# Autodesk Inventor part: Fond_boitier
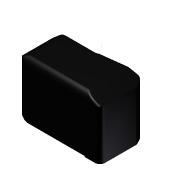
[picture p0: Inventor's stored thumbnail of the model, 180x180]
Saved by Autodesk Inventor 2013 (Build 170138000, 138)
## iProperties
Created: 2011-07
Part Number: Fond_boitier
Document SubType Name: Modeling
Designer: domi
Density: 1 g/cm^3
Material: Générique
Author: domi
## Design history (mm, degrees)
sketch "Esquisse1"
  geometry: L1 (-13.986, -11.692)-(16.704, -11.692) reference; L2 (18.504, -9.892)-(18.504, 4.208) reference; L3 (18.352, 4.844)-(17.078, 7.344) reference; L4 (15.831, 8.108)-(12.304, 8.108) reference; L5 (9.472, 9.948)-(7.197, 15.058) reference; L6 (6.731, 15.749)-(4.851, 17.696) reference; L7 (-10.621, 14.519)-(-16.593, 4.961) reference; L8 (16.704, -10.292)-(-13.986, -10.292) reference; L9 (-15.406, 4.219)-(-9.678, 13.386) reference; L10 (4.275, 16.278)-(5.724, 14.777) reference; L11 (5.918, 14.489)-(8.193, 9.378) reference; L12 (12.304, 6.708)-(15.831, 6.708) reference; L13 (15.831, 6.708)-(17.104, 4.208) reference; L14 (17.104, 4.208)-(17.104, -9.892) reference; L15 (16.704, -12.092)-(-13.986, -12.092); L16 (-16.932, 5.173)-(-10.891, 14.841); L17 (5.017, 18.1)-(7.018, 16.027); L18 (7.562, 15.221)-(9.838, 10.11); L19 (12.304, 8.508)-(15.831, 8.508); L20 (17.434, 7.526)-(18.708, 5.026); L21 (18.904, 4.208)-(18.904, -9.892); A1 r 1.8 centre (16.704, -9.892) between (16.704, -11.692) and (18.504, -9.892) reference; A2 r 1.4 centre (17.104, 4.208) between (18.504, 4.208) and (18.352, 4.844) reference; A3 r 1.4 centre (15.831, 6.708) between (17.078, 7.344) and (15.831, 8.108) reference; A4 r 3.1 centre (12.304, 11.208) between (9.472, 9.948) and (12.304, 8.108) reference; A5 r 2.4 centre (5.004, 14.082) between (7.197, 15.058) and (6.731, 15.749) reference; A6 r 44.4 centre (5.904, -26.692) between (4.851, 17.696) and (-10.621, 14.519) reference; A7 r 21.8 centre (1.894, -6.592) between (-16.593, 4.961) and (-19.878, -5.495) reference; A8 r 5.9 centre (-13.986, -5.792) between (-19.878, -5.495) and (-13.986, -11.692) reference; A9 r 4.5 centre (-13.986, -5.792) between (-18.48, -5.565) and (-13.986, -10.292) reference; A10 r 20.4 centre (1.894, -6.592) between (-15.406, 4.219) and (-18.48, -5.565) reference; A11 r 43 centre (5.904, -26.692) between (4.275, 16.278) and (-9.678, 13.386) reference; A12 r 1 centre (5.004, 14.082) between (5.918, 14.489) and (5.724, 14.777) reference; A13 r 4.5 centre (12.304, 11.208) between (8.193, 9.378) and (12.304, 6.708) reference; A14 r 0.4 centre (16.704, -9.892) between (16.704, -10.292) and (17.104, -9.892) reference; A15 r 6.3 centre (-13.986, -5.792) between (-20.278, -5.475) and (-13.986, -12.092); A16 r 22.2 centre (1.894, -6.592) between (-16.932, 5.173) and (-20.278, -5.475); A17 r 44.8 centre (5.904, -26.692) between (5.017, 18.1) and (-10.891, 14.841); A18 r 2.8 centre (5.004, 14.082) between (7.562, 15.221) and (7.018, 16.027); A19 r 2.7 centre (12.304, 11.208) between (9.838, 10.11) and (12.304, 8.508); A20 r 1.8 centre (15.831, 6.708) between (17.434, 7.526) and (15.831, 8.508); A21 r 1.8 centre (17.104, 4.208) between (18.904, 4.208) and (18.708, 5.026); A22 r 2.2 centre (16.704, -9.892) between (16.704, -12.092) and (18.904, -9.892); 1 further point
  constraints: 16 point on circle, 14 end point, 8 centre point, 14 other
  dimensions: "d0" = 1.8 distance between parallel lines of L8 L15
extrude "Corps" new body sketch "Esquisse1" distance "d1" = 25.5; taper "d2" = 0 deg
node "Plan de construction1"
sketch "Esquisse4"
  geometry: L1 (-16.704, -12.092)-(13.986, -12.092) reference; L2 (16.932, 5.173)-(10.891, 14.841) reference; L3 (-5.017, 18.1)-(-7.018, 16.027) reference; L4 (-7.562, 15.221)-(-9.838, 10.11) reference; L5 (-12.304, 8.508)-(-15.831, 8.508) reference; L6 (-17.434, 7.526)-(-18.708, 5.026) reference; L7 (-18.904, 4.208)-(-18.904, -9.892) reference; C1 r 1.77 at (1.596, 9.208) reference; A1 r 6.3 centre (13.986, -5.792) between (13.986, -12.092) and (20.278, -5.475) reference; A2 r 22.2 centre (-1.894, -6.592) between (20.278, -5.475) and (16.932, 5.173) reference; A3 r 44.8 centre (-5.904, -26.692) between (10.891, 14.841) and (-5.017, 18.1) reference; A4 r 2.8 centre (-5.004, 14.082) between (-7.018, 16.027) and (-7.562, 15.221) reference; A5 r 2.7 centre (-12.304, 11.208) between (-12.304, 8.508) and (-9.838, 10.11) reference; A6 r 1.8 centre (-15.831, 6.708) between (-15.831, 8.508) and (-17.434, 7.526) reference; A7 r 1.8 centre (-17.104, 4.208) between (-18.708, 5.026) and (-18.904, 4.208) reference; A8 r 2.2 centre (-16.704, -9.892) between (-18.904, -9.892) and (-16.704, -12.092) reference; 1 further point
  node "Référence2"
node "Axe de construction1"
sketch "Esquisse5"
  geometry: L1 (13.986, -12.092)-(-16.704, -12.092) reference; L2 (-18.904, -9.892)-(-18.904, 4.208) reference; L3 (-18.708, 5.026)-(-17.434, 7.526) reference; L4 (-15.831, 8.508)-(-12.304, 8.508) reference; L5 (-9.838, 10.11)-(-7.562, 15.221) reference; L6 (-7.018, 16.027)-(-5.017, 18.1) reference; L7 (10.891, 14.841)-(16.932, 5.173) reference; L8 (16.473, 5.908)-(1.596, 5.908); L9 (-12.304, 8.508)-(-2.132, 7.614); A1 r 6.3 centre (13.986, -5.792) between (13.986, -12.092) and (20.278, -5.475) reference; A2 r 2.2 centre (-16.704, -9.892) between (-18.904, -9.892) and (-16.704, -12.092) reference; A3 r 1.8 centre (-17.104, 4.208) between (-18.708, 5.026) and (-18.904, 4.208) reference; A4 r 1.8 centre (-15.831, 6.708) between (-15.831, 8.508) and (-17.434, 7.526) reference; A5 r 2.7 centre (-12.304, 11.208) between (-12.304, 8.508) and (-9.838, 10.11) reference; A6 r 2.8 centre (-5.004, 14.082) between (-7.018, 16.027) and (-7.562, 15.221) reference; A7 r 44.8 centre (-5.904, -26.692) between (10.891, 14.841) and (-5.017, 18.1) reference; A8 r 22.2 centre (-1.894, -6.592) between (20.278, -5.475) and (16.932, 5.173) reference; A9 r 3.3 centre (1.596, 9.208) between (-0.834, 6.975) and (1.596, 5.908); A10 r 2 centre (-2.307, 5.622) between (-0.834, 6.975) and (-2.132, 7.614); 2 further points
  constraints: 4 end point, 4 point on circle, 3 tangent, 2 centre point, 1 coincident, 1 parallel, 1 point on line
  dimensions: "d10" = 6.6 diameter of A9; "d108" = 2 radius of A10
extrude "Complement corps" cut sketch "Esquisse5" stored distance "d11" = 1.8; taper "d12" = 0 deg
sketch "Esquisse6"
  geometry: L1 (0, 0)-(0, 25.5) reference; L2 (30.69, 0)-(0, 0) reference; L3 (30.69, 0)-(30.69, 25.5) reference; L4 (32.89, 0)-(32.89, 25.5) reference; L5 (32.89, 22.5)-(25.89, 25.5); L6 (25.89, 25.5)-(32.89, 25.5); L7 (32.89, 25.5)-(32.89, 22.5); L8 (30.69, 25.5)-(0, 25.5) reference; 1 further point
  constraints: 6 end point, 1 collinear, 1 perpendicular, 1 point on line
  dimensions: "d14" = 3 distance of L4.end L5.start; "d15" = 7 distance of L5.end L4.end
extrude "Chanfrein 1" cut sketch "Esquisse6" stored distance "d16" = 1.8; taper "d17" = 0 deg
sketch "Esquisse7"
  geometry: L1 (0, 0)-(-22.5, 0) reference; L2 (0, 14.1)-(0, 0) reference; L3 (0, 14.1)-(-22.5, 14.1) reference; L4 (0, -2.2)-(-25.5, -2.2) reference; L5 (0, -2.2)-(-23.443, -2.2) reference; L6 (-25.6, 18.329)-(-25.6, 16.6) reference; L7 (-25.6, 16.6)-(-25.6, 14.6) reference; L8 (-25.6, 4.417)-(-25.6, 14.6) reference; L9 (-25.6, -2.2)-(-25.6, 4.417) reference; L10 (-22.6, 0.8)-(-25.6, 0.8); L11 (-22.6, 0.8)-(-22.6, -2.2); L12 (-22.6, -2.2)-(-25.6, -2.2); L13 (-25.6, -2.2)-(-25.6, 0.8); L14 (-25.6, -2.2)-(-25.6, 18.329) reference; L15 (-23.443, -2.2)-(-25.5, -2.2) reference; L16 (-22.5, 14.1)-(-22.5, 0) reference; A1 r 3 centre (-22.6, 0.8) between (-25.6, 0.8) and (-22.6, -2.2); 1 further point
  constraints: 8 end point, 4 tangent, 2 perpendicular, 2 point on circle, 2 point on line, 1 centre point, 1 collinear
  dimensions: "d18" = 6 diameter of A1
extrude "Arrondi1" cut sketch "Esquisse7" stored distance "d19" = 1.8; taper "d20" = 0 deg
fillet "Congé1" dims "d53" = 1
node "Plan de construction chanfrein 2"
  node "Axe de construction2"
sketch "Esquisse8"
  geometry: L1 (11.1, -11.807)-(11.1, -8.084); L2 (11.1, -11.807)-(11.1, -17.224); L3 (0, 15.601)-(0, -2) reference; L4 (-11, -2)-(-11, -12.287) reference; L5 (-11, -12.287)-(-25.5, -12.287) reference; L6 (-25.5, -12.287)-(-25.5, 17.851) reference; L7 (-25.5, 17.851)-(-2.9, 17.851) reference; L8 (-6, -2)-(0, -1); L9 (-8.744, -2.457)-(0, -2.457); L10 (0, -2)-(0, -2.457); L11 (-6, -2)-(-8.744, -2.457); L12 (0, -2)-(-11, -2) reference; 3 further points; 1 other entity
  constraints: 12 end point, 1 collinear, 1 parallel, 1 perpendicular, 1 point on line, 1 other
  dimensions: "d109" = 6 distance from line of L3 L8.start; "d112" = 1.45727 distance from line of L8.end L9
extrude "Chanfein2" cut sketch "Esquisse8" stored distance "d24" = 1.8; taper "d25" = 0 deg
sketch "Esquisse9"
  geometry: L1 (0, -1)-(0, -2) reference; L2 (0, -2)-(-6, -2) reference; L3 (0, -1)-(-6, -2) reference; L4 (0, 15.601)-(0, -1) reference; L5 (-11, -2)-(-11, -12.287) reference; L6 (-6, -2)-(-11, -2) reference; L7 (-25.5, 17.851)-(-2.9, 17.851) reference; L8 (-25.5, -12.287)-(-25.5, 17.851) reference; L9 (-11, -12.287)-(-25.5, -12.287) reference; 3 further points; 1 other entity
  constraints: 1 other
extrude "Suite chanfrein2" cut sketch "Esquisse9" distance "d26" = 3.904; taper "d27" = 0 deg
sketch "Esquisse10"
  geometry: L1 (-3.813, 14.5)-(-3.813, -11) reference; L2 (0, -11)-(-3.813, -11); A1 r 6 centre (2.187, -5) between (-3.813, -5) and (2.187, -11); 9 further points
  constraints: 2 end point, 2 point on circle, 2 point on line, 2 tangent, 1 centre point, 1 perpendicular, 2 other
  dimensions: "d107" = 6 distance from line of L2 A1.start
extrude "Arrondi2" cut sketch "Esquisse10" stored distance "d30" = 3.904; taper "d31" = 0 deg
sketch "Esquisse2"
  geometry: L1 (-16.704, -12.092)-(13.986, -12.092) reference; L2 (16.932, 5.173)-(10.891, 14.841) reference; L3 (-16.704, -11.692)-(13.986, -11.692); L4 (16.593, 4.961)-(10.621, 14.519); L5 (-4.851, 17.696)-(-6.731, 15.749); L6 (-7.197, 15.058)-(-9.472, 9.948); L7 (-12.304, 8.108)-(-15.831, 8.108); L8 (-17.078, 7.344)-(-18.352, 4.844); L9 (-18.504, 4.208)-(-18.504, -9.892); L10 (-5.017, 18.1)-(-7.018, 16.027) reference; L11 (-7.562, 15.221)-(-9.838, 10.11) reference; L12 (-12.304, 8.508)-(-15.831, 8.508) reference; L13 (-17.434, 7.526)-(-18.708, 5.026) reference; L14 (-18.904, 4.208)-(-18.904, -9.892) reference; A1 r 6.3 centre (13.986, -5.792) between (13.986, -12.092) and (20.278, -5.475) reference; A2 r 22.2 centre (-1.894, -6.592) between (20.278, -5.475) and (16.932, 5.173) reference; A3 r 44.8 centre (-5.904, -26.692) between (10.891, 14.841) and (-5.017, 18.1) reference; A4 r 2.2 centre (-16.704, -9.892) between (-18.904, -9.892) and (-16.704, -12.092) reference; A5 r 5.9 centre (13.986, -5.792) between (13.986, -11.692) and (19.878, -5.495); A6 r 21.8 centre (-1.894, -6.592) between (19.878, -5.495) and (16.593, 4.961); A7 r 44.4 centre (-5.904, -26.692) between (10.621, 14.519) and (-4.851, 17.696); A8 r 2.4 centre (-5.004, 14.082) between (-6.731, 15.749) and (-7.197, 15.058); A9 r 3.1 centre (-12.304, 11.208) between (-12.304, 8.108) and (-9.472, 9.948); A10 r 1.4 centre (-15.831, 6.708) between (-15.831, 8.108) and (-17.078, 7.344); A11 r 1.4 centre (-17.104, 4.208) between (-18.352, 4.844) and (-18.504, 4.208); A12 r 1.8 centre (-16.704, -9.892) between (-18.504, -9.892) and (-16.704, -11.692); A13 r 2.8 centre (-5.004, 14.082) between (-7.018, 16.027) and (-7.562, 15.221) reference; A14 r 2.7 centre (-12.304, 11.208) between (-12.304, 8.508) and (-9.838, 10.11) reference; A15 r 1.8 centre (-15.831, 6.708) between (-15.831, 8.508) and (-17.434, 7.526) reference; A16 r 1.8 centre (-17.104, 4.208) between (-18.708, 5.026) and (-18.904, 4.208) reference; 1 further point
  constraints: 16 point on circle, 14 end point, 8 centre point, 4 other
extrude "Epaulement Languette" cut sketch "Esquisse2" distance "d4" = 1; taper "d5" = 0 deg
sketch "Esquisse15"
  geometry: L1 (-16.704, -11.692)-(13.986, -11.692) reference; L2 (13.986, -12.092)-(-16.704, -12.092) reference; L3 (-18.504, 4.208)-(-18.504, -9.892) reference; L4 (-18.904, -9.892)-(-18.904, 4.208) reference; L5 (-17.078, 7.344)-(-18.352, 4.844) reference; L6 (-18.708, 5.026)-(-17.434, 7.526) reference; L7 (-12.304, 8.108)-(-15.831, 8.108) reference; L8 (-15.831, 8.508)-(-12.304, 8.508) reference; L9 (-11.904, -12.092)-(-11.904, -11.692); L10 (-11.904, -11.692)-(-16.704, -11.692); L11 (-11.904, -12.092)-(-16.704, -12.092); L12 (-9.838, 10.11)-(-7.562, 15.221) reference; L13 (-7.197, 15.058)-(-9.472, 9.948) reference; L14 (-9.158, 10.653)-(-9.247, 10.693); L15 (-9.247, 10.693)-(-9.523, 10.816); L16 (-9.158, 10.653)-(-9.472, 9.948); L17 (-9.523, 10.816)-(-9.838, 10.11); A1 r 1.8 centre (-16.704, -9.892) between (-18.504, -9.892) and (-16.704, -11.692) reference; A2 r 2.2 centre (-16.704, -9.892) between (-18.904, -9.892) and (-16.704, -12.092) reference; A3 r 1.4 centre (-17.104, 4.208) between (-18.352, 4.844) and (-18.504, 4.208) reference; A4 r 1.8 centre (-17.104, 4.208) between (-18.708, 5.026) and (-18.904, 4.208) reference; A5 r 1.8 centre (-15.831, 6.708) between (-15.831, 8.508) and (-17.434, 7.526) reference; A6 r 1.4 centre (-15.831, 6.708) between (-15.831, 8.108) and (-17.078, 7.344) reference; A7 r 2.7 centre (-12.304, 11.208) between (-12.304, 8.508) and (-9.838, 10.11) reference; A8 r 3.1 centre (-12.304, 11.208) between (-12.304, 8.108) and (-9.472, 9.948) reference; 3 further points
  constraints: 14 end point, 4 point on line, 3 collinear, 3 perpendicular, 3 tangent, 1 point on circle
  dimensions: "d49" = 7 distance between parallel lines of L4 L9; "d50" = 22.7848 distance from line of L2 L14.end
extrude "Non languette" join sketch "Esquisse15" distance "d51" = 1 (= d4); taper "d52" = 0 deg
sketch "Esquisse11"
  geometry: C1 r 5.1 at (0, 5.1); 2 further points
  constraints: 1 centre point, 1 coincident
  dimensions: "d33" = 10.2 diameter of C1
extrude "Bossage inter_1" join sketch "Esquisse11" distance "d34" = 2.35; taper "d35" = 0 deg
sketch "Esquisse12"
  geometry: C1 r 3.75 at (-1.596, 9.208); 2 further points
  constraints: 1 centre point, 1 coincident
  dimensions: "d36" = 7.5 diameter of C1
extrude "Bossage exter_1" join sketch "Esquisse12" distance "d37" = 1; taper "d38" = 0 deg
sketch "Esquisse13"
  geometry: C1 r 3.75 at (0, 0); 2 further points
  constraints: 1 centre point, 1 coincident
  dimensions: "d39" = 7.5 diameter of C1
extrude "Trou lamé inter_1" cut sketch "Esquisse13" distance "d40" = 1.85; taper "d41" = 0 deg
sketch "Esquisse14"
  geometry: 2 further points
hole "Trou lamé exter_1" sketch "Esquisse14" at (0, 0) diameter "d42" = 4.5; stored, may be unused: countersink angle "d46" = 90 deg, drill point angle "d48" = 118 deg; dims "d43" = 6, "d44" = 6.5, "d45" = 1, "d47" = 8
node "Plan Nervure1"
sketch "Esquisse16"
  geometry: L1 (8.509, 0)-(6.709, 0) reference; L2 (-12.092, 0)-(-12.092, 22.6) reference; L3 (-6.092, 23.494)-(-6.092, 13.394); L4 (1.408, 23.494)-(1.408, 19.7); L5 (8.509, 14.5)-(8.509, 0) reference; L6 (8.504, 21.717)-(8.504, 14.5) reference; L7 (7.893, 25.352)-(8.504, 21.717) reference; L8 (-9.892, 25.352)-(7.893, 25.352) reference; L9 (8.504, 14.5)-(8.509, 14.5) reference; L10 (6.709, 0)-(6.709, 12.7) reference; L11 (6.709, 12.7)-(6.697, 12.7) reference; L12 (6.697, 12.7)-(6.697, 21.527) reference; L13 (6.697, 21.527)-(6.383, 23.394) reference; L14 (6.383, 23.394)-(-9.992, 23.394) reference; L15 (-10.292, 22.6)-(-10.292, 0) reference; L16 (-10.292, 0)-(-12.092, 0) reference; A1 r 3 centre (-9.092, 22.6) between (-10.756, 25.096) and (-12.092, 22.6) reference; A2 r 1.2 centre (-9.092, 22.6) between (-9.992, 23.394) and (-10.292, 22.6) reference; 1 further point
  constraints: 4 end point, 1 parallel, 1 other
  dimensions: "d60" = 19.7 distance from line of L1 L4.end; "d61" = 6 distance between parallel lines of L2 L3; "d62" = 7.5 distance between parallel lines of L3 L4; "d92" = 10.1 distance of L3.start L3.end
feature "Nervure1" sketch "Esquisse16" dims "d63" = 1, "d64" = 1, "d65" = 0
node "Plan Nervure 2"
sketch "Esquisse17"
  geometry: L1 (0.123, 21.379)-(0.123, 2); L2 (2.229, 0)-(-10.337, 0); L3 (-2.877, 21.379)-(-2.877, 2); L4 (0.123, 2)-(-2.877, 2); L5 (0.123, 2)-(0.123, 0); L6 (-2.877, 2)-(-2.877, 0); L7 (-9.68, 0)-(-11.24, 0) reference; L8 (-11.24, 0)-(-11.24, 1) reference; L9 (-11.24, 1)-(-11.671, 1) reference; L10 (-11.671, 1)-(-11.671, 24.133) reference; L11 (5.908, 25.169)-(5.908, 14.5) reference; L12 (5.908, 14.5)-(6.265, 14.5) reference; L13 (6.265, 14.5)-(6.265, 1) reference; L14 (6.265, 1)-(5.51, 1) reference; L15 (5.51, 1)-(5.51, 0) reference; L16 (-10.64, 25.169)-(5.908, 25.169) reference; L17 (2.733, 0)-(2.733, 23.212) reference; L18 (2.733, 23.212)-(-9.68, 23.212) reference; L19 (-9.68, 23.212)-(-9.68, 0) reference; L20 (5.51, 0)-(2.733, 0) reference; A1 r 3 centre (-9.092, 22.6) between (-10.64, 25.169) and (-11.671, 24.133) reference; 1 further point
  constraints: 12 end point, 6 perpendicular, 2 point on line
  dimensions: "d67" = 3 distance between parallel lines of L3 L1; "d72" = 2 distance between parallel lines of L2 L4
feature "Nervure2" sketch "Esquisse17" dims "d69" = 1, "d70" = 1, "d71" = 0
sketch "Esquisse18"
  geometry: C1 r 2.25 at (0, 0) reference; C2 r 3.75 at (0, 0) reference; C3 r 3.4 at (0, 0)
  constraints: 1 centre point, 1 coincident
  dimensions: "d89" = 6.8 diameter of C3
extrude "logement joint" cut sketch "Esquisse18" distance "d90" = 1.8; taper "d91" = 0 deg
sketch "Esquisse19"
  geometry: L1 (11.641, 13.018)-(11.641, 0.808) reference; L2 (0.441, 9.048)-(0.441, 3.24) reference; L3 (0.441, 13.768)-(0.441, 9.048) reference; L4 (0.441, 3.24)-(0.441, 0.858) reference; L5 (0.441, 0.858)-(11.641, 0.858) reference; L6 (5.441, 13.768)-(10.077, 13.768) reference; L7 (0.241, 11.018)-(11.841, 11.018); L8 (11.841, 11.018)-(11.841, 1.018); L9 (11.841, 1.018)-(0.241, 1.018); L10 (0.241, 1.018)-(0.241, 11.018); L11 (-2.654, 6.018)-(14.204, 6.018); L12 (11.641, 13.018)-(1.641, 13.018) reference; 1 further point
  constraints: 24 end point, 4 horizontal, 4 vertical, 2 parallel, 2 perpendicular, 13 other
  dimensions: "d117" = 10 distance between parallel lines of L9 L7; "d120" = 0.2 distance between parallel lines of L3 L10; "d121" = 0.2 distance between parallel lines of L8 L1 (derived); "d122" = 12.1595 distance between parallel lines of L5 L12 (derived); "d123" = 14 diameter of L12 L11
extrude "évidemment pour cage moteur" cut sketch "Esquisse19" distance "d118" = 0.3; taper "d119" = 0 deg
node "Solide1"
node "Corps solides"
node "Corps surfaciques"
feature "Coque" dims "d32" = 1.8
node "Référence1"
node "Boucle projetée1"
node "Boucle projetée3"
node "Boucle projetée4"
node "Boucle projetée5"
node "Boucle projetée6"
node "Projeter les arêtes coupées1"
node "Projeter les arêtes coupées2"
node "Projeter les arêtes coupées4"
node "Projeter les arêtes coupées5"
node "Projeter les arêtes coupées6"
other parameters: "d8" = -14.5, "d58" = 12.25, "d66" = -16.25, "d100" = 1.23918
